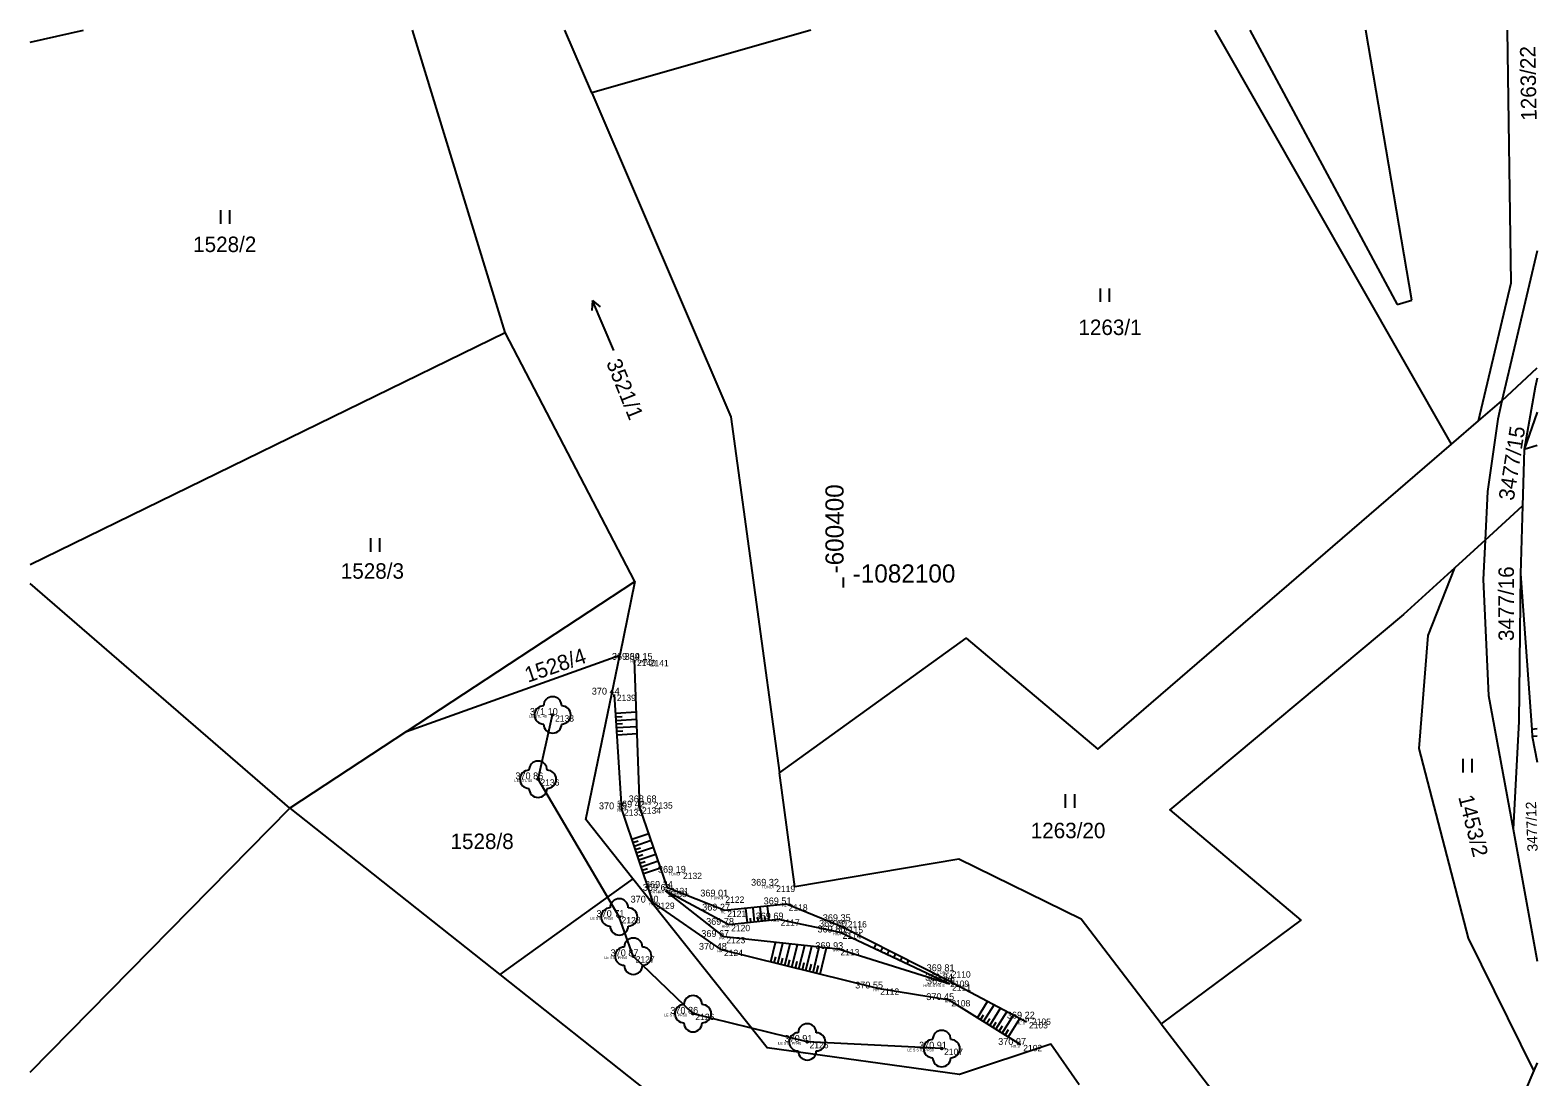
# Model space of a CAD drawing. Extents: x -600490 to -600324, y -1082221 to -1082039.
# Drawn here: x -600489.5 to -600323.6, y -1082154.4 to -1082039.2 of the extents above; entities that cross this region are included whole.
import ezdxf

# ---------------------------------------------------------------- set-up
doc = ezdxf.new("R2010")
doc.units = 0
for name, color, linetype in [('1-Body', 7, 'Continuous'), ('14-Ter-hrany-vodní-plochy', 7, 'Continuous'), ('2-Čísla-bodů', 7, 'Continuous'), ('20-Bod-výškopisu', 7, 'Continuous'), ('21-Zeleň-linie', 7, 'Continuous'), ('22-Zeleň-stromy', 7, 'Continuous'), ('3-Výšky-bodů', 7, 'Continuous'), ('63-Měřická-síť', 7, 'Continuous'), ('Level 48', 7, 'Continuous')]:
    doc.layers.add(name, color=color, linetype=linetype)

msp = doc.modelspace()

# ---------------------------------------------------------------- linework, layer by layer
at = {"layer": '1-Body'}
for p, q in [((-600423, -1082108.5), (-600423, -1082108.5)), ((-600421.59, -1082108.51), (-600421.59, -1082108.51)), ((-600425.21, -1082112.33), (-600425.21, -1082112.33)), ((-600432.02, -1082114.57), (-600432.02, -1082114.57)), ((-600433.62, -1082121.65), (-600433.62, -1082121.65)), ((-600424.42, -1082124.95), (-600424.42, -1082124.95)), ((-600422.44, -1082124.75), (-600422.44, -1082124.75)), ((-600421.15, -1082124.18), (-600421.15, -1082124.18)), ((-600417.93, -1082131.93), (-600417.93, -1082131.93)), ((-600419.36, -1082133.6), (-600419.36, -1082133.6)), ((-600407.68, -1082133.36), (-600407.68, -1082133.36)), ((-600420.94, -1082135.22), (-600420.94, -1082135.22)), ((-600419.6, -1082133.92), (-600419.6, -1082133.92)), ((-600413.27, -1082134.55), (-600413.27, -1082134.55)), ((-600406.3, -1082135.41), (-600406.3, -1082135.41)), ((-600424.69, -1082136.8), (-600424.69, -1082136.8)), ((-600413.06, -1082136.1), (-600413.06, -1082136.1)), ((-600407.18, -1082137.07), (-600407.18, -1082137.07)), ((-600412.63, -1082137.67), (-600412.63, -1082137.67)), ((-600400.37, -1082138.51), (-600400.37, -1082138.51)), ((-600400.2, -1082137.88), (-600400.2, -1082137.88)), ((-600399.79, -1082137.26), (-600399.79, -1082137.26)), ((-600413.16, -1082139), (-600413.16, -1082139)), ((-600400.61, -1082140.33), (-600400.61, -1082140.33)), ((-600423.14, -1082141.12), (-600423.14, -1082141.12)), ((-600413.42, -1082140.41), (-600413.42, -1082140.41)), ((-600388.36, -1082142.77), (-600388.36, -1082142.77)), ((-600396.23, -1082144.67), (-600396.23, -1082144.67)), ((-600388.53, -1082143.8), (-600388.53, -1082143.8)), ((-600388.32, -1082144.21), (-600388.32, -1082144.21)), ((-600388.4, -1082145.95), (-600388.4, -1082145.95)), ((-600416.57, -1082147.45), (-600416.57, -1082147.45)), ((-600379.86, -1082148.37), (-600379.86, -1082148.37)), ((-600379.53, -1082147.98), (-600379.53, -1082147.98)), ((-600404, -1082150.55), (-600404, -1082150.55)), ((-600389.2, -1082151.29), (-600389.2, -1082151.29)), ((-600380.49, -1082150.88), (-600380.49, -1082150.88))]:
    msp.add_line(p, q, dxfattribs=at)
at = {"layer": '14-Ter-hrany-vodní-plochy'}
for p, q in [((-600422.44, -1082124.75), (-600423, -1082108.5)), ((-600424.42, -1082124.95), (-600425.21, -1082112.33)), ((-600425.083, -1082114.366), (-600422.803, -1082114.223)), ((-600425.058, -1082114.765), (-600424.377, -1082114.723)), ((-600425.033, -1082115.164), (-600422.775, -1082115.023)), ((-600425.008, -1082115.564), (-600424.334, -1082115.522)), ((-600424.983, -1082115.963), (-600422.748, -1082115.823)), ((-600424.958, -1082116.362), (-600424.29, -1082116.32)), ((-600424.933, -1082116.761), (-600422.72, -1082116.623)), ((-600420.94, -1082135.22), (-600424.42, -1082124.95)), ((-600419.36, -1082133.6), (-600422.44, -1082124.75)), ((-600423.306, -1082128.238), (-600421.446, -1082127.607)), ((-600423.178, -1082128.617), (-600422.618, -1082128.427)), ((-600423.049, -1082128.996), (-600421.183, -1082128.363)), ((-600422.921, -1082129.374), (-600422.36, -1082129.184)), ((-600422.792, -1082129.753), (-600420.92, -1082129.119)), ((-600422.664, -1082130.132), (-600422.101, -1082129.941)), ((-600422.536, -1082130.511), (-600420.657, -1082129.874)), ((-600422.407, -1082130.89), (-600421.843, -1082130.698)), ((-600422.279, -1082131.269), (-600420.394, -1082130.63)), ((-600422.151, -1082131.647), (-600421.584, -1082131.455)), ((-600422.022, -1082132.026), (-600420.131, -1082131.385)), ((-600413.06, -1082136.1), (-600419.36, -1082133.6)), ((-600413.42, -1082140.41), (-600420.94, -1082135.22)), ((-600413.16, -1082139), (-600419.6, -1082133.92)), ((-600412.63, -1082137.67), (-600419.6, -1082133.92)), ((-600406.3, -1082135.41), (-600413.06, -1082136.1)), ((-600400.2, -1082137.88), (-600406.3, -1082135.41)), ((-600407.18, -1082137.07), (-600412.63, -1082137.67)), ((-600410.589, -1082137.445), (-600410.762, -1082135.865)), ((-600410.191, -1082137.401), (-600410.243, -1082136.928)), ((-600409.793, -1082137.358), (-600409.967, -1082135.784)), ((-600409.396, -1082137.314), (-600409.448, -1082136.843)), ((-600408.998, -1082137.27), (-600409.171, -1082135.703)), ((-600408.601, -1082137.226), (-600408.652, -1082136.757)), ((-600408.203, -1082137.183), (-600408.375, -1082135.622)), ((-600400.37, -1082138.51), (-600407.18, -1082137.07)), ((-600388.32, -1082144.21), (-600400.37, -1082138.51)), ((-600388.53, -1082143.8), (-600400.2, -1082137.88)), ((-600400.61, -1082140.33), (-600413.16, -1082139)), ((-600408.024, -1082141.747), (-600407.492, -1082139.601)), ((-600407.248, -1082141.94), (-600406.689, -1082139.686)), ((-600406.471, -1082142.132), (-600405.886, -1082139.771)), ((-600405.695, -1082142.325), (-600405.083, -1082139.856)), ((-600404.918, -1082142.517), (-600404.28, -1082139.941)), ((-600404.142, -1082142.709), (-600403.477, -1082140.026)), ((-600403.365, -1082142.902), (-600402.673, -1082140.111)), ((-600402.588, -1082143.094), (-600401.87, -1082140.196)), ((-600388.32, -1082144.21), (-600400.61, -1082140.33)), ((-600396.637, -1082140.276), (-600396.413, -1082139.801)), ((-600396.276, -1082140.447), (-600396.21, -1082140.307)), ((-600395.914, -1082140.618), (-600395.699, -1082140.163)), ((-600396.23, -1082144.67), (-600413.42, -1082140.41)), ((-600407.636, -1082141.843), (-600407.472, -1082141.183)), ((-600406.859, -1082142.036), (-600406.688, -1082141.344)), ((-600406.083, -1082142.228), (-600405.903, -1082141.504)), ((-600405.306, -1082142.421), (-600405.119, -1082141.664)), ((-600404.53, -1082142.613), (-600404.334, -1082141.824)), ((-600403.753, -1082142.806), (-600403.55, -1082141.985)), ((-600395.553, -1082140.789), (-600395.49, -1082140.655)), ((-600395.191, -1082140.96), (-600394.986, -1082140.525)), ((-600394.829, -1082141.131), (-600394.769, -1082141.003)), ((-600394.468, -1082141.302), (-600394.272, -1082140.887)), ((-600394.106, -1082141.473), (-600394.049, -1082141.352)), ((-600393.745, -1082141.644), (-600393.558, -1082141.249)), ((-600393.383, -1082141.815), (-600393.329, -1082141.7)), ((-600393.022, -1082141.986), (-600392.844, -1082141.611)), ((-600402.977, -1082142.998), (-600402.765, -1082142.145)), ((-600388.4, -1082145.95), (-600396.23, -1082144.67)), ((-600379.86, -1082148.37), (-600388.53, -1082143.8)), ((-600380.49, -1082150.88), (-600388.4, -1082145.95)), ((-600385.275, -1082147.898), (-600384.157, -1082146.105)), ((-600384.596, -1082148.321), (-600383.448, -1082146.479)), ((-600383.917, -1082148.744), (-600382.738, -1082146.853)), ((-600384.935, -1082148.109), (-600384.595, -1082147.564)), ((-600384.256, -1082148.533), (-600383.907, -1082147.973)), ((-600383.577, -1082148.956), (-600383.219, -1082148.381)), ((-600383.238, -1082149.167), (-600382.029, -1082147.227)), ((-600382.559, -1082149.59), (-600381.319, -1082147.601)), ((-600381.88, -1082150.014), (-600380.609, -1082147.975)), ((-600382.898, -1082149.379), (-600382.531, -1082148.789)), ((-600382.219, -1082149.802), (-600381.843, -1082149.198))]:
    msp.add_line(p, q, dxfattribs=at)
at = {"layer": '21-Zeleň-linie'}
for p, q in [((-600433.62, -1082121.65), (-600432.02, -1082114.57)), ((-600424.69, -1082136.8), (-600433.62, -1082121.65)), ((-600423.14, -1082141.12), (-600424.69, -1082136.8)), ((-600416.57, -1082147.45), (-600423.14, -1082141.12)), ((-600404, -1082150.55), (-600416.57, -1082147.45)), ((-600389.2, -1082151.29), (-600404, -1082150.55))]:
    msp.add_line(p, q, dxfattribs=at)
at = {"layer": '22-Zeleň-stromy'}
for centre in [(-600432.02, -1082114.57), (-600433.62, -1082121.65), (-600424.69, -1082136.8), (-600423.14, -1082141.12), (-600416.57, -1082147.45), (-600404, -1082150.55), (-600389.2, -1082151.29)]:
    msp.add_circle(centre, 0.1, dxfattribs=at)
for centre, start, end in [((-600433.02, -1082114.57), 90, 270), ((-600432.02, -1082113.57), 0, 180), ((-600431.02, -1082114.57), 270, 90), ((-600432.02, -1082115.57), 180, 0), ((-600433.62, -1082120.65), 0, 180), ((-600434.62, -1082121.65), 90, 270), ((-600432.62, -1082121.65), 270, 90), ((-600433.62, -1082122.65), 180, 0), ((-600424.69, -1082135.8), 0, 180), ((-600425.69, -1082136.8), 90, 270), ((-600423.69, -1082136.8), 270, 90), ((-600424.69, -1082137.8), 180, 0), ((-600424.14, -1082141.12), 90, 270), ((-600423.14, -1082140.12), 0, 180), ((-600422.14, -1082141.12), 270, 90), ((-600423.14, -1082142.12), 180, 0), ((-600417.57, -1082147.45), 90, 270), ((-600416.57, -1082146.45), 0, 180), ((-600415.57, -1082147.45), 270, 90), ((-600416.57, -1082148.45), 180, 0), ((-600404, -1082149.55), 0, 180), ((-600405, -1082150.55), 90, 270), ((-600403, -1082150.55), 270, 90), ((-600390.2, -1082151.29), 90, 270), ((-600389.2, -1082150.29), 0, 180), ((-600388.2, -1082151.29), 270, 90), ((-600404, -1082151.55), 180, 0), ((-600389.2, -1082152.29), 180, 0)]:
    msp.add_arc(centre, 1, start, end, dxfattribs=at)
at = {"layer": 'Level 48'}
for p, q in [((-600489.514, -1082040.516), (-600483.65, -1082039.203)), ((-600437.26, -1082072.49), (-600447.442, -1082039.203)), ((-600427.7, -1082046.11), (-600430.66, -1082039.203)), ((-600403.61, -1082039.203), (-600427.7, -1082046.11)), ((-600333.1, -1082084.78), (-600359.104, -1082039.203)), ((-600355.289, -1082039.203), (-600339.1, -1082069.41)), ((-600337.48, -1082068.91), (-600342.524, -1082039.203)), ((-600427.7, -1082046.11), (-600412.41, -1082081.75)), ((-600468.531, -1082060.53), (-600468.531, -1082059.03)), ((-600467.53, -1082060.53), (-600467.53, -1082059.03)), ((-600427.621, -1082068.949), (-600427.701, -1082070.045)), ((-600425.277, -1082074.472), (-600427.621, -1082068.949)), ((-600427.621, -1082068.949), (-600426.778, -1082069.653)), ((-600371.731, -1082069.12), (-600371.731, -1082067.62)), ((-600370.73, -1082069.12), (-600370.73, -1082067.62)), ((-600339.1, -1082069.41), (-600337.48, -1082068.91)), ((-600489.514, -1082098.02), (-600437.26, -1082072.49)), ((-600422.96, -1082099.87), (-600437.26, -1082072.49)), ((-600327.55, -1082079.99), (-600323.676, -1082076.354)), ((-600323.91, -1082078.5), (-600325.09, -1082085.36)), ((-600323.676, -1082077.516), (-600323.91, -1082078.5)), ((-600330.13, -1082082.21), (-600327.55, -1082079.99)), ((-600412.41, -1082081.75), (-600407.06, -1082120.94)), ((-600323.676, -1082081.242), (-600325.09, -1082085.36)), ((-600325.09, -1082085.36), (-600325.28, -1082091.56)), ((-600323.676, -1082084.92), (-600325.09, -1082085.36)), ((-600329.41, -1082095.33), (-600325.28, -1082091.56)), ((-600325.28, -1082091.56), (-600325.52, -1082099.04)), ((-600452.031, -1082096.61), (-600452.031, -1082095.11)), ((-600451.03, -1082096.61), (-600451.03, -1082095.11)), ((-600329.41, -1082095.33), (-600332.75, -1082098.38)), ((-600460.95, -1082124.84), (-600489.514, -1082100.1)), ((-600448.11, -1082116.4), (-600422.96, -1082099.87)), ((-600422.96, -1082099.87), (-600424.64, -1082107.98)), ((-600325.52, -1082099.04), (-600324.28, -1082116.16)), ((-600448.11, -1082116.4), (-600424.64, -1082107.98)), ((-600428.38, -1082126.08), (-600424.64, -1082107.98)), ((-600329.02, -1082112.44), (-600326.33, -1082127.13)), ((-600448.11, -1082116.4), (-600460.95, -1082124.84)), ((-600323.676, -1082116.102), (-600324.28, -1082116.16)), ((-600324.28, -1082116.16), (-600324.22, -1082116.96)), ((-600323.676, -1082116.901), (-600324.22, -1082116.96)), ((-600324.22, -1082116.96), (-600323.676, -1082119.754)), ((-600331.821, -1082120.89), (-600331.821, -1082119.39)), ((-600330.82, -1082120.89), (-600330.82, -1082119.39)), ((-600375.571, -1082124.79), (-600375.571, -1082123.29)), ((-600374.57, -1082124.79), (-600374.57, -1082123.29)), ((-600489.514, -1082153.899), (-600460.95, -1082124.84)), ((-600460.95, -1082124.84), (-600437.82, -1082143.15)), ((-600423.2, -1082132.6), (-600428.38, -1082126.08)), ((-600326.33, -1082127.13), (-600323.676, -1082141.652)), ((-600423.2, -1082132.6), (-600437.82, -1082143.15)), ((-600324.04, -1082153.7), (-600331.23, -1082139.15)), ((-600437.82, -1082143.15), (-600421.71, -1082155.91)), ((-600323.676, -1082152.853), (-600324.04, -1082153.7)), ((-600324.04, -1082153.7), (-600331.06, -1082170.06))]:
    msp.add_line(p, q, dxfattribs=at)
for points in [[(-600330.13, -1082082.21), (-600326.55, -1082067.01), (-600326.923, -1082039.203)], [(-600323.676, -1082063.509), (-600324.55, -1082067.23), (-600327.55, -1082079.99)], [(-600327.55, -1082079.99), (-600328.02, -1082082), (-600329.14, -1082089.98), (-600329.41, -1082095.33)], [(-600407.06, -1082120.94), (-600386.52, -1082106.11), (-600372.03, -1082118.33), (-600333.1, -1082084.78), (-600330.13, -1082082.21)], [(-600329.41, -1082095.33), (-600329.62, -1082099.65), (-600329.02, -1082112.44)], [(-600332.75, -1082098.38), (-600338.37, -1082103.52), (-600364.1, -1082125.01), (-600349.69, -1082137.17), (-600363.76, -1082147.61), (-600365.05, -1082148.57)], [(-600331.23, -1082139.15), (-600336.68, -1082118.25), (-600335.66, -1082105.83), (-600332.75, -1082098.38)], [(-600400, -1082100.55), (-600400, -1082100), (-600400, -1082099.45)], [(-600325.52, -1082099.04), (-600325.7, -1082115.29), (-600326.33, -1082127.13)], [(-600365.05, -1082148.57), (-600373.87, -1082137.04), (-600387.33, -1082130.46), (-600405.35, -1082133.5), (-600407.06, -1082120.94)], [(-600374.07, -1082155.26), (-600377.2, -1082150.79), (-600387.25, -1082154.15), (-600408.42, -1082151.19), (-600423.2, -1082132.6)], [(-600365.05, -1082148.57), (-600354.03, -1082162.96), (-600354.93, -1082192.29), (-600353.55, -1082197.21), (-600349.92, -1082202.09), (-600344.89, -1082207.45)]]:
    msp.add_lwpolyline(points, dxfattribs=at)

# ---------------------------------------------------------------- texts
at = {"layer": '2-Čísla-bodů'}
for s, p in [(' 2140', (-600423, -1082109.2)), (' 2141', (-600421.59, -1082109.21)), (' 2139', (-600425.21, -1082113.03)), (' 2138', (-600432.01, -1082115.3)), (' 2136', (-600433.62, -1082122.35)), (' 2133', (-600424.42, -1082125.65)), (' 2134', (-600422.44, -1082125.45)), (' 2135', (-600421.15, -1082124.88)), (' 2132', (-600417.93, -1082132.63)), (' 2131', (-600419.36, -1082134.3)), (' 2119', (-600407.68, -1082134.06)), (' 2129', (-600420.94, -1082135.92)), (' 2130', (-600419.6, -1082134.62)), (' 2122', (-600413.27, -1082135.25)), (' 2118', (-600406.3, -1082136.11)), (' 2128', (-600424.69, -1082137.5)), (' 2121', (-600413.06, -1082136.8)), (' 2117', (-600407.18, -1082137.77)), (' 2120', (-600412.63, -1082138.37)), (' 2114', (-600400.37, -1082139.21)), (' 2115', (-600400.2, -1082138.58)), (' 2116', (-600399.79, -1082137.96)), (' 2123', (-600413.16, -1082139.7)), (' 2113', (-600400.61, -1082141.03)), (' 2127', (-600423.14, -1082141.82)), (' 2124', (-600413.42, -1082141.11)), (' 2110', (-600388.36, -1082143.47)), (' 2112', (-600396.23, -1082145.37)), (' 2109', (-600388.53, -1082144.5)), (' 2111', (-600388.32, -1082144.91)), (' 2108', (-600388.4, -1082146.65)), (' 2126', (-600416.57, -1082148.15)), (' 2103', (-600379.86, -1082149.07)), (' 2105', (-600379.53, -1082148.68)), (' 2125', (-600404, -1082151.25)), (' 2107', (-600389.2, -1082151.99)), (' 2102', (-600380.49, -1082151.58))]:
    msp.add_text(s, height=0.7, dxfattribs=at).set_placement(p)
at = {"layer": '20-Bod-výškopisu'}
for p in [(-600421.59, -1082108.51), (-600421.59, -1082108.51), (-600421.15, -1082124.18), (-600421.15, -1082124.18), (-600417.93, -1082131.93), (-600417.93, -1082131.93), (-600407.68, -1082133.36), (-600407.68, -1082133.36), (-600413.27, -1082134.55), (-600413.27, -1082134.55), (-600399.79, -1082137.26), (-600399.79, -1082137.26), (-600388.36, -1082142.77), (-600388.36, -1082142.77), (-600379.53, -1082147.98)]:
    msp.add_text('.', height=0.1, dxfattribs=at).set_placement(p)
at = {"layer": '3-Výšky-bodů'}
for s, p in [('369 34 ', (-600425.5, -1082108.5)), ('369 15 ', (-600424.09, -1082108.51)), ('370 44 ', (-600427.71, -1082112.33)), ('371 10 ', (-600434.52, -1082114.57)), ('370 86 ', (-600436.12, -1082121.65)), ('368 68 ', (-600423.65, -1082124.18)), ('370 15 ', (-600426.92, -1082124.95)), ('369 42 ', (-600424.94, -1082124.75)), ('369 19 ', (-600420.43, -1082131.93)), ('369 62 ', (-600422.1, -1082133.92)), ('369 34 ', (-600421.86, -1082133.6)), ('369 32 ', (-600410.18, -1082133.36)), ('370 40 ', (-600423.44, -1082135.22)), ('369 01 ', (-600415.77, -1082134.55)), ('369 27 ', (-600415.56, -1082136.1)), ('369 51 ', (-600408.8, -1082135.41)), ('370 71 ', (-600427.19, -1082136.8)), ('369 78 ', (-600415.13, -1082137.67)), ('369 69 ', (-600409.68, -1082137.07)), ('369 35 ', (-600402.29, -1082137.26)), ('369 67 ', (-600415.66, -1082139)), ('369 86 ', (-600402.87, -1082138.51)), ('369 60 ', (-600402.7, -1082137.88)), ('370 87 ', (-600425.64, -1082141.12)), ('370 48 ', (-600415.92, -1082140.41)), ('369 93 ', (-600403.11, -1082140.33)), ('369 81 ', (-600390.86, -1082142.77)), ('369 84 ', (-600391.03, -1082143.8)), ('369 89 ', (-600390.82, -1082144.21)), ('370 55 ', (-600398.73, -1082144.67)), ('370 45 ', (-600390.9, -1082145.95)), ('370 86 ', (-600419.07, -1082147.45)), ('369 22 ', (-600382.03, -1082147.98)), ('370 91 ', (-600406.5, -1082150.55)), ('370 97 ', (-600382.99, -1082150.88)), ('370 91 ', (-600391.7, -1082151.29))]:
    msp.add_text(s, height=0.75, dxfattribs=at).set_placement(p)
at = {"layer": '63-Měřická-síť'}
for s, p in [('HL', (-600423.475, -1082108.8)), ('T DNO', (-600422.991, -1082108.81)), ('T', (-600421.79, -1082108.81)), ('HR', (-600425.699, -1082112.63)), ('LE STL 40', (-600434.619, -1082114.87)), ('LE STL 40', (-600436.219, -1082121.95)), ('HR', (-600424.909, -1082125.25)), ('HL', (-600422.915, -1082125.05)), ('T DNO', (-600422.551, -1082124.48)), ('T', (-600421.35, -1082124.48)), ('T DNO', (-600419.331, -1082132.23)), ('T', (-600418.13, -1082132.23)), ('HL', (-600419.835, -1082133.9)), ('T DNO', (-600409.081, -1082133.66)), ('T', (-600407.88, -1082133.66)), ('HR', (-600421.429, -1082135.52)), ('PA HRA', (-600421.3, -1082134.22)), ('T DNO', (-600414.671, -1082134.85)), ('T', (-600413.47, -1082134.85)), ('HL', (-600406.775, -1082135.71)), ('LE STL PR50', (-600427.889, -1082137.1)), ('HL', (-600413.535, -1082136.4)), ('HRA', (-600407.98, -1082137.37)), ('HRA', (-600413.43, -1082137.97)), ('T DNO', (-600401.191, -1082137.56)), ('HRA', (-600401.17, -1082138.81)), ('HL', (-600400.675, -1082138.18)), ('T', (-600399.99, -1082137.56)), ('PA', (-600413.66, -1082139.3)), ('PA', (-600401.11, -1082140.63)), ('LE STL PR50', (-600426.339, -1082141.42)), ('HR', (-600413.909, -1082140.71)), ('T DNO', (-600389.761, -1082143.07)), ('T', (-600388.56, -1082143.07)), ('HR', (-600396.719, -1082144.97)), ('HRA S PA S', (-600391.209, -1082144.51)), ('HL', (-600389.005, -1082144.1)), ('HR', (-600388.889, -1082146.25)), ('LE STL PR50', (-600419.769, -1082147.75)), ('T DNO', (-600380.931, -1082148.28)), ('HL S', (-600380.949, -1082148.67)), ('T', (-600379.76, -1082148.28)), ('T', (-600379.73, -1082148.28)), ('LE STL PR40', (-600407.199, -1082150.85)), ('LE S STL PR30', (-600392.999, -1082151.59)), ('HR S', (-600381.579, -1082151.18))]:
    msp.add_text(s, height=0.3, dxfattribs=at).set_placement(p)
at = {"layer": 'Level 48'}
for s, height, rotation, p in [('1263/22', 1.7, 91, (-600323.733, -1082049.158)), ('3521/1', 1.7, 292, (-600426.154, -1082075.799)), ('3477/15', 1.7, 81, (-600326.261, -1082091.052)), ('-600400', 2, 90, (-600400, -1082099)), ('3477/16', 1.7, 90, (-600326.235, -1082106.436)), ('1528/4', 1.7, 19, (-600434.741, -1082111.031)), ('1453/2', 1.7, 284, (-600332.37, -1082123.589)), ('3477/12', 1.139, 92, (-600323.609, -1082129.583))]:
    msp.add_text(s, height=height, rotation=rotation, dxfattribs=at).set_placement(p)
for s, height, p in [('1528/2', 1.7, (-600471.58, -1082063.625)), ('1263/1', 1.7, (-600374.16, -1082072.755)), ('1528/3', 1.7, (-600455.33, -1082099.575)), ('-1082100', 2, (-600399, -1082100)), ('1263/20', 1.7, (-600379.406, -1082128.135)), ('1528/8', 1.7, (-600443.256, -1082129.325))]:
    msp.add_text(s, height=height, dxfattribs=at).set_placement(p)

doc.saveas('drawing.dxf')
